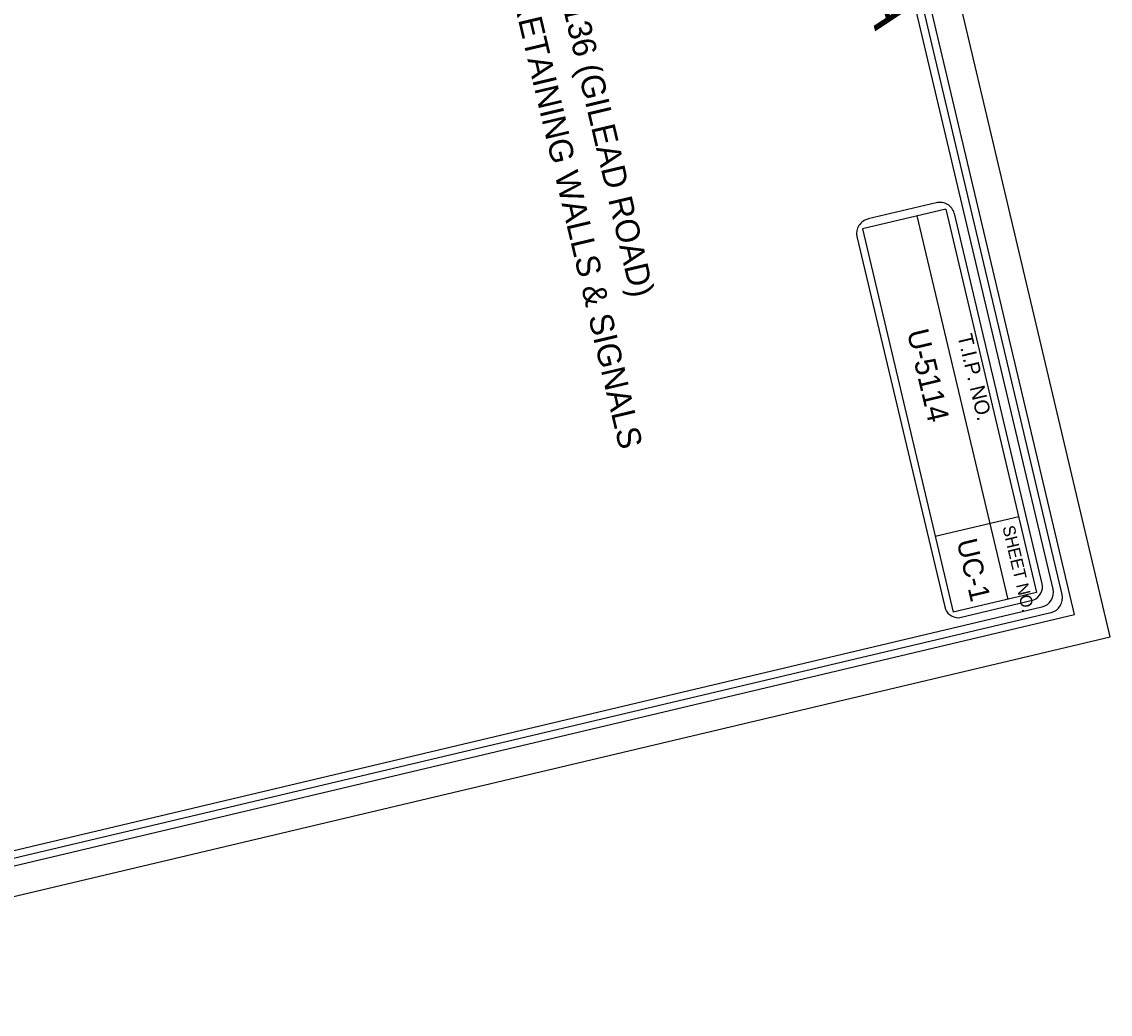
# Model space of a CAD drawing. Extents: x 1439200 to 3815465, y 598050 to 1224643.
# Drawn here: x 1442416 to 1445633, y 598050 to 600981 of the extents above; entities that cross this region are included whole.
import ezdxf

# ---------------------------------------------------------------- set-up
doc = ezdxf.new("R2010")
doc.units = 0
doc.layers.add('Exist Right of Way Line', color=7, linetype='Continuous')
doc.layers.add('Old_Level_5', color=7, linetype='Continuous')

msp = doc.modelspace()

# ---------------------------------------------------------------- linework, layer by layer
at = {"layer": 'Exist Right of Way Line'}
msp.add_lwpolyline([(1439298.8, 605293.4), (1440988.4, 598155.9), (1445527, 599230.3), (1443837.3, 606367.8)], close=True, dxfattribs=at)
at = {"layer": 'Old_Level_5'}
for p, q in [((1445118.1, 600446.2), (1444918, 600398.9)), ((1445147.1, 600428), (1444900.5, 600369.6)), ((1445147.1, 600428), (1445415.2, 599295.5)), ((1445431.8, 599321.2), (1445172.2, 600415.3)), ((1445061.8, 600407.8), (1445329.9, 599275.3)), ((1444884.4, 600347.4), (1445144, 599253.3)), ((1444900.5, 600369.6), (1445168.5, 599237.1)), ((1445362.3, 599518.9), (1445115.7, 599460.6)), ((1445415.2, 599295.5), (1445168.5, 599237.1))]:
    msp.add_line(p, q, dxfattribs=at)
msp.add_lwpolyline([(1445632.9, 599164.9), (1443909.8, 606443.8), (1439200, 605328.8), (1440923.1, 598050)], close=True, dxfattribs=at)
for points in [[(1445490.4, 599289.4), (1443990.3, 605626.4)], [(1445463.9, 599305.8), (1444024.6, 605385.7)], [(1441856, 598406.5), (1445431.2, 599252.8)], [(1445184.6, 599220.8), (1445406.7, 599273.4)], [(1441047.6, 598192.5), (1445457.7, 599236.5)]]:
    msp.add_lwpolyline(points, dxfattribs=at)
for centre in [(1445421.3, 599295.7), (1445447.8, 599279.3)]:
    msp.add_arc(centre, 44, 283.3181, 13.3181, dxfattribs=at)
for centre, major_axis, ratio, start_param, end_param in [((1445128.1, 600405), (43.9, 10.4), 0.941469, 0.000468, 1.571265), ((1444928.1, 600357.5), (-43.9, -10.4), 0.941469, 4.712857, 6.283654), ((1445387.7, 599310.8), (43.9, 10.4), 0.926296, 4.933032, 6.283554), ((1445187.7, 599263.4), (-43.9, -10.4), 0.941469, 0.000472, 1.282481)]:
    msp.add_ellipse(centre, major_axis=major_axis, ratio=ratio, start_param=start_param, end_param=end_param, dxfattribs=at)

# ---------------------------------------------------------------- texts
for s, height, rotation, p in [('STATE OF NORTH CAROLINA', 135.18, 283.3466, (1444349.2, 603434.4)), ('TYPE OF WORK: GRADING, PAVING, DRAINAGE, RETAINING WALLS & SIGNALS', 70.155, 283.3038, (1443358.5, 603204.5)), ('LOCATION: US-21 (STATESVILLE ROAD) AND SR 2136 (GILEAD ROAD)', 70.155, 283.3038, (1443493.9, 603227)), ('U-5114', 63.64, 283.3466, (1445031.8, 600065.5)), ('T.I.P. NO.', 43.92, 283.3466, (1445181.2, 600053.6)), ('SHEET NO.', 36.29, 283.3466, (1445313.9, 599488.8)), ('UC-1', 59.89, 283.3466, (1445178.7, 599446.7))]:
    msp.add_text(s, height=height, rotation=rotation, dxfattribs=at).set_placement(p)

doc.saveas('drawing.dxf')
